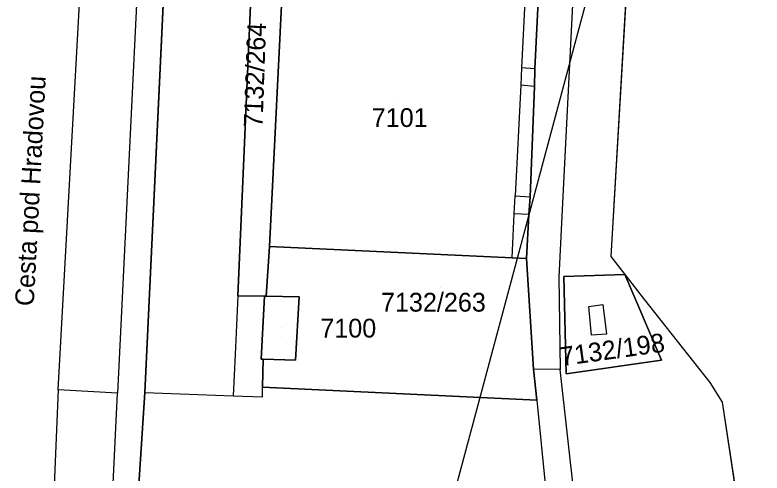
# Model space of a CAD drawing. Extents: x -266199 to -261993, y -1239047 to -1235108.
# Drawn here: x -263519.4 to -263440, y -1236556.5 to -1236507.7 of the extents above; entities that cross this region are included whole.
import ezdxf

# ---------------------------------------------------------------- set-up
doc = ezdxf.new("R2010")
doc.units = 0
for name, color, linetype in [('body_kn', 7, 'Continuous'), ('kladpar_druhypozemkov', 7, 'Continuous'), ('kladpar_hranice', 7, 'Continuous'), ('kladpar_parcelnecisla', 7, 'Continuous'), ('kladpar_plochy', 7, 'Continuous'), ('kladpar_sipky', 7, 'Continuous'), ('popisy', 7, 'Continuous'), ('zappar_hrandruhpozemk', 7, 'Continuous'), ('zuob_linie', 7, 'Continuous'), ('zuob_plochy', 7, 'Continuous')]:
    doc.layers.add(name, color=color, linetype=linetype)

msp = doc.modelspace()

# ---------------------------------------------------------------- linework, layer by layer
at = {"layer": 'body_kn'}
for p, q in [((-263465.55, -1236513.38), (-263465.55, -1236513.38)), ((-263464.14, -1236513.47), (-263464.14, -1236513.47)), ((-263464.14, -1236513.47), (-263464.14, -1236513.47)), ((-263465.64, -1236515.22), (-263465.64, -1236515.22)), ((-263464.17, -1236515.35), (-263464.17, -1236515.35)), ((-263464.17, -1236515.35), (-263464.17, -1236515.35)), ((-263466.23, -1236527.01), (-263466.23, -1236527.01)), ((-263466.23, -1236527.01), (-263466.23, -1236527.01)), ((-263464.66, -1236527.09), (-263464.66, -1236527.09)), ((-263466.33, -1236528.91), (-263466.33, -1236528.91)), ((-263466.33, -1236528.91), (-263466.33, -1236528.91)), ((-263464.77, -1236528.97), (-263464.77, -1236528.97)), ((-263464.77, -1236528.97), (-263464.77, -1236528.97)), ((-263461.26, -1236529.16), (-263461.26, -1236529.16)), ((-263492.36, -1236532.38), (-263492.36, -1236532.38)), ((-263492.36, -1236532.38), (-263492.36, -1236532.38)), ((-263456.08, -1236533.46), (-263456.08, -1236533.46)), ((-263466.56, -1236533.6), (-263466.56, -1236533.6)), ((-263466.56, -1236533.6), (-263466.56, -1236533.6)), ((-263465.03, -1236533.67), (-263465.03, -1236533.67)), ((-263461.59, -1236535.65), (-263461.59, -1236535.65)), ((-263461.06, -1236535.59), (-263461.06, -1236535.59)), ((-263454.57, -1236535.38), (-263454.57, -1236535.38)), ((-263495.75, -1236537.64), (-263495.75, -1236537.64)), ((-263495.75, -1236537.64), (-263495.75, -1236537.64)), ((-263492.91, -1236537.68), (-263492.91, -1236537.68)), ((-263492.91, -1236537.68), (-263492.91, -1236537.68)), ((-263492.71, -1236537.68), (-263492.71, -1236537.68)), ((-263489.22, -1236537.73), (-263489.22, -1236537.73)), ((-263452.47, -1236538.05), (-263452.47, -1236538.05)), ((-263458.4, -1236538.78), (-263458.4, -1236538.78)), ((-263458.4, -1236538.78), (-263458.4, -1236538.78)), ((-263456.93, -1236538.56), (-263456.93, -1236538.56)), ((-263458.13, -1236541.83), (-263458.13, -1236541.83)), ((-263456.54, -1236541.73), (-263456.54, -1236541.73)), ((-263496.03, -1236543.88), (-263496.03, -1236543.88)), ((-263493.24, -1236544.38), (-263493.24, -1236544.38)), ((-263493.04, -1236544.38), (-263493.04, -1236544.38)), ((-263489.61, -1236544.47), (-263489.61, -1236544.47)), ((-263450.67, -1236544.49), (-263450.67, -1236544.49)), ((-263464.29, -1236545.43), (-263464.29, -1236545.43)), ((-263461.45, -1236545.47), (-263461.45, -1236545.47)), ((-263460.82, -1236545.94), (-263460.82, -1236545.94)), ((-263460.82, -1236545.94), (-263460.82, -1236545.94)), ((-263445.53, -1236546.86), (-263445.53, -1236546.86)), ((-263445.53, -1236546.86), (-263445.53, -1236546.86)), ((-263514.84, -1236547.63), (-263514.84, -1236547.63)), ((-263514.84, -1236547.63), (-263514.84, -1236547.63)), ((-263493.1, -1236547.36), (-263493.1, -1236547.36)), ((-263508.53, -1236548), (-263508.53, -1236548)), ((-263508.53, -1236548), (-263508.53, -1236548)), ((-263505.62, -1236547.93), (-263505.62, -1236547.93)), ((-263505.62, -1236547.93), (-263505.62, -1236547.93)), ((-263496.22, -1236548.28), (-263496.22, -1236548.28)), ((-263493.12, -1236548.39), (-263493.12, -1236548.39)), ((-263463.95, -1236548.74), (-263463.95, -1236548.74)), ((-263463.95, -1236548.74), (-263463.95, -1236548.74)), ((-263444.22, -1236548.96), (-263444.22, -1236548.96)), ((-263444.22, -1236548.96), (-263444.22, -1236548.96))]:
    msp.add_line(p, q, dxfattribs=at)
at = {"layer": 'kladpar_druhypozemkov'}
for p, q in [((-263479.1, -1236516.55), (-263479.1, -1236516.55)), ((-263474.15, -1236536.76), (-263474.15, -1236536.76)), ((-263457.52, -1236539.9), (-263457.52, -1236539.9)), ((-263491.12, -1236540.99), (-263491.12, -1236540.99))]:
    msp.add_line(p, q, dxfattribs=at)
at = {"layer": 'kladpar_hranice'}
for p, q in [((-263396.48, -1236274.15), (-263473.03, -1236559.71)), ((-263445.53, -1236546.86), (-263444.22, -1236548.96))]:
    msp.add_line(p, q, dxfattribs=at)
for points in [[(-263456.85, -1236458.14), (-263456.9, -1236474.58), (-263455.57, -1236476.25), (-263455.13, -1236476.8), (-263453.78, -1236478.79), (-263453.17, -1236479.7), (-263452.89, -1236483.66), (-263452.74, -1236485.43), (-263452.69, -1236486.04), (-263452.2, -1236486.96), (-263454.13, -1236500.19), (-263456.08, -1236533.46), (-263454.57, -1236535.38), (-263461.06, -1236535.59), (-263460.82, -1236545.94), (-263450.67, -1236544.49), (-263454.57, -1236535.38), (-263452.47, -1236538.05), (-263445.53, -1236546.86)], [(-263493.38, -1236483.86), (-263495.75, -1236537.64), (-263492.91, -1236537.68), (-263493.24, -1236544.38), (-263493.04, -1236544.38), (-263493.1, -1236547.36), (-263463.95, -1236548.74), (-263464.29, -1236545.43), (-263465.03, -1236533.67), (-263464.77, -1236528.97), (-263464.66, -1236527.09), (-263464.17, -1236515.35), (-263464.14, -1236513.47), (-263463.54, -1236501.25), (-263463.55, -1236490.7), (-263463.55, -1236489.97), (-263463.55, -1236487.7), (-263463.55, -1236486.74), (-263463.41, -1236482.34), (-263465.54, -1236482.23)], [(-263502.57, -1236483.44), (-263505.62, -1236547.93), (-263506.94, -1236568.11), (-263507.88, -1236582.39)], [(-263507.88, -1236582.39), (-263506.94, -1236568.11), (-263505.62, -1236547.93), (-263502.57, -1236483.44), (-263493.38, -1236483.86)], [(-263490.73, -1236496.51), (-263490.85, -1236501.72), (-263492.36, -1236532.38), (-263492.71, -1236537.68), (-263492.91, -1236537.68), (-263495.75, -1236537.64), (-263493.38, -1236483.86)], [(-263492.36, -1236532.38), (-263490.85, -1236501.72), (-263489.95, -1236501.76), (-263479.84, -1236502.15), (-263479.78, -1236500.58), (-263478.06, -1236500.68), (-263471.78, -1236500.87), (-263470.24, -1236500.94), (-263463.54, -1236501.25), (-263464.14, -1236513.47), (-263464.17, -1236515.35), (-263464.66, -1236527.09), (-263464.77, -1236528.97), (-263465.03, -1236533.67), (-263466.56, -1236533.6), (-263492.36, -1236532.38)], [(-263466.56, -1236533.6), (-263465.03, -1236533.67), (-263464.29, -1236545.43), (-263463.95, -1236548.74), (-263493.1, -1236547.36), (-263493.04, -1236544.38), (-263489.61, -1236544.47), (-263489.22, -1236537.73), (-263492.71, -1236537.68), (-263492.36, -1236532.38), (-263466.56, -1236533.6)], [(-263460.82, -1236545.94), (-263461.06, -1236535.59), (-263454.57, -1236535.38), (-263450.67, -1236544.49), (-263460.82, -1236545.94)], [(-263492.91, -1236537.68), (-263492.71, -1236537.68), (-263489.22, -1236537.73), (-263489.61, -1236544.47), (-263493.04, -1236544.38), (-263493.24, -1236544.38), (-263492.91, -1236537.68)], [(-263444.22, -1236548.96), (-263442.35, -1236561.28), (-263441.75, -1236565.24), (-263441.38, -1236567.71), (-263441.21, -1236568.34), (-263456.21, -1236570.33), (-263457.14, -1236570.46), (-263455.53, -1236586.76), (-263456.81, -1236587.09), (-263459.98, -1236587.91), (-263507.69, -1236600.3), (-263509.41, -1236600.75), (-263511.92, -1236601.4), (-263515.67, -1236602.37), (-263515.78, -1236599.49), (-263516.23, -1236587.58), (-263511.28, -1236583.61), (-263510.14, -1236583.67), (-263507.88, -1236582.39)]]:
    msp.add_lwpolyline(points, dxfattribs=at)
at = {"layer": 'kladpar_plochy'}
for p, q in [((-263505.62, -1236547.93), (-263502.57, -1236483.44)), ((-263493.38, -1236483.86), (-263495.75, -1236537.64)), ((-263454.13, -1236500.19), (-263456.08, -1236533.46)), ((-263464.14, -1236513.47), (-263463.54, -1236501.25)), ((-263464.17, -1236515.35), (-263464.14, -1236513.47)), ((-263464.66, -1236527.09), (-263464.17, -1236515.35)), ((-263464.77, -1236528.97), (-263464.66, -1236527.09)), ((-263465.03, -1236533.67), (-263464.77, -1236528.97)), ((-263456.08, -1236533.46), (-263454.57, -1236535.38)), ((-263464.29, -1236545.43), (-263465.03, -1236533.67)), ((-263454.57, -1236535.38), (-263461.06, -1236535.59)), ((-263461.06, -1236535.59), (-263460.82, -1236545.94)), ((-263450.67, -1236544.49), (-263454.57, -1236535.38)), ((-263454.57, -1236535.38), (-263452.47, -1236538.05)), ((-263495.75, -1236537.64), (-263492.91, -1236537.68)), ((-263492.91, -1236537.68), (-263493.24, -1236544.38)), ((-263452.47, -1236538.05), (-263445.53, -1236546.86)), ((-263493.24, -1236544.38), (-263493.04, -1236544.38)), ((-263493.04, -1236544.38), (-263493.1, -1236547.36)), ((-263460.82, -1236545.94), (-263450.67, -1236544.49)), ((-263463.95, -1236548.74), (-263464.29, -1236545.43)), ((-263445.53, -1236546.86), (-263444.22, -1236548.96)), ((-263493.1, -1236547.36), (-263463.95, -1236548.74)), ((-263506.94, -1236568.11), (-263505.62, -1236547.93)), ((-263444.22, -1236548.96), (-263442.35, -1236561.28))]:
    msp.add_line(p, q, dxfattribs=at)
msp.add_lwpolyline([(-263501.28, -1236460.62), (-263502.42, -1236480.32), (-263502.57, -1236483.44), (-263505.62, -1236547.93), (-263506.94, -1236568.11), (-263507.88, -1236582.39), (-263510.14, -1236583.67), (-263511.28, -1236583.61), (-263516.23, -1236587.58), (-263515.78, -1236599.49), (-263515.67, -1236602.37), (-263515.39, -1236603.81), (-263514.37, -1236608.96), (-263511.25, -1236627.28), (-263508.75, -1236638.71), (-263497.36, -1236689.19)], dxfattribs=at)
for points in [[(-263490.73, -1236496.51), (-263490.85, -1236501.72), (-263492.36, -1236532.38), (-263492.71, -1236537.68), (-263492.91, -1236537.68), (-263495.75, -1236537.64), (-263493.38, -1236483.86), (-263489.96, -1236484.12), (-263490.26, -1236486.65), (-263490.4, -1236489.76)], [(-263492.36, -1236532.38), (-263490.85, -1236501.72), (-263489.95, -1236501.76), (-263479.84, -1236502.15), (-263479.78, -1236500.58), (-263478.06, -1236500.68), (-263471.78, -1236500.87), (-263470.24, -1236500.94), (-263463.54, -1236501.25), (-263464.14, -1236513.47), (-263464.17, -1236515.35), (-263464.66, -1236527.09), (-263464.77, -1236528.97), (-263465.03, -1236533.67), (-263466.56, -1236533.6)], [(-263466.56, -1236533.6), (-263465.03, -1236533.67), (-263464.29, -1236545.43), (-263463.95, -1236548.74), (-263493.1, -1236547.36), (-263493.04, -1236544.38), (-263489.61, -1236544.47), (-263489.22, -1236537.73), (-263492.71, -1236537.68), (-263492.36, -1236532.38)], [(-263460.82, -1236545.94), (-263461.06, -1236535.59), (-263454.57, -1236535.38), (-263450.67, -1236544.49)], [(-263492.91, -1236537.68), (-263492.71, -1236537.68), (-263489.22, -1236537.73), (-263489.61, -1236544.47), (-263493.04, -1236544.38), (-263493.24, -1236544.38)]]:
    msp.add_lwpolyline(points, close=True, dxfattribs=at)
at = {"layer": 'kladpar_sipky'}
msp.add_line((-263490.58, -1236542.61), (-263490.58, -1236542.61), dxfattribs=at)
at = {"layer": 'zappar_hrandruhpozemk'}
for p, q in [((-263514.84, -1236547.63), (-263511.42, -1236485.97)), ((-263505.53, -1236486.4), (-263508.53, -1236548)), ((-263464.14, -1236513.47), (-263465.55, -1236513.38)), ((-263464.17, -1236515.35), (-263465.64, -1236515.22)), ((-263466.33, -1236528.91), (-263466.23, -1236527.01)), ((-263466.23, -1236527.01), (-263464.66, -1236527.09)), ((-263466.56, -1236533.6), (-263466.33, -1236528.91)), ((-263464.77, -1236528.97), (-263466.33, -1236528.91)), ((-263495.75, -1236537.64), (-263496.03, -1236543.88)), ((-263458.4, -1236538.78), (-263456.93, -1236538.56)), ((-263456.93, -1236538.56), (-263456.54, -1236541.73)), ((-263493.12, -1236548.39), (-263493.1, -1236547.36)), ((-263505.62, -1236547.93), (-263496.22, -1236548.28)), ((-263463.95, -1236548.74), (-263460.29, -1236584.82))]:
    msp.add_line(p, q, dxfattribs=at)
for points in [[(-263460.97, -1236456.12), (-263459.99, -1236458.89), (-263459.35, -1236461.61), (-263460.01, -1236503.79), (-263461.26, -1236529.16)], [(-263465.02, -1236502.72), (-263465.55, -1236513.38), (-263465.64, -1236515.22), (-263466.23, -1236527.01)], [(-263461.26, -1236529.16), (-263461.59, -1236535.65), (-263461.45, -1236545.47)], [(-263456.54, -1236541.73), (-263458.13, -1236541.83), (-263458.4, -1236538.78)], [(-263496.03, -1236543.88), (-263496.22, -1236548.28), (-263493.12, -1236548.39)], [(-263456.81, -1236587.09), (-263461.45, -1236545.47), (-263464.29, -1236545.43)], [(-263508.53, -1236548), (-263514.84, -1236547.63), (-263516.09, -1236577.37)], [(-263516.09, -1236577.37), (-263509.95, -1236577.58), (-263508.53, -1236548)]]:
    msp.add_lwpolyline(points, dxfattribs=at)
at = {"layer": 'zuob_linie'}
msp.add_lwpolyline([(-263456.85, -1236458.14), (-263456.9, -1236474.58), (-263455.57, -1236476.25), (-263455.13, -1236476.8), (-263453.78, -1236478.79), (-263453.17, -1236479.7), (-263452.89, -1236483.66), (-263452.74, -1236485.43), (-263452.69, -1236486.04), (-263452.2, -1236486.96), (-263454.13, -1236500.19), (-263456.08, -1236533.46), (-263454.57, -1236535.38), (-263452.47, -1236538.05), (-263445.53, -1236546.86), (-263444.22, -1236548.96), (-263442.35, -1236561.28)], dxfattribs=at)
at = {"layer": 'zuob_plochy'}
msp.add_lwpolyline([(-263456.85, -1236458.14), (-263456.9, -1236474.58), (-263455.57, -1236476.25), (-263455.13, -1236476.8), (-263453.78, -1236478.79), (-263453.17, -1236479.7), (-263452.89, -1236483.66), (-263452.74, -1236485.43), (-263452.69, -1236486.04), (-263452.2, -1236486.96), (-263454.13, -1236500.19), (-263456.08, -1236533.46), (-263454.57, -1236535.38), (-263452.47, -1236538.05), (-263445.53, -1236546.86), (-263444.22, -1236548.96), (-263442.35, -1236561.28)], dxfattribs=at)

# ---------------------------------------------------------------- texts
at = {"layer": 'kladpar_parcelnecisla'}
for s, rotation, p in [('7132/264', 88, (-263493.11, -1236519.752)), ('7132/198', 8, (-263461.273, -1236545.12))]:
    msp.add_text(s, height=2, rotation=rotation, dxfattribs=at).set_placement(p)
for s, p in [('7101', (-263481.495, -1236519.67)), ('7132/263', (-263480.513, -1236539.32)), ('7100', (-263486.966, -1236542.08))]:
    msp.add_text(s, height=2, dxfattribs=at).set_placement(p)
at = {"layer": 'popisy'}
msp.add_text('Cesta pod Hradovou', height=2, rotation=87, dxfattribs=at).set_placement((-263517.444, -1236538.77))

doc.saveas('drawing.dxf')
